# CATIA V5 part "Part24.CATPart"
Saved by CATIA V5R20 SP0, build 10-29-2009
Part number: 9SA200018-C_acabado
Revision: ANY
Definition: UNKNOWN
Nomenclature: 9SA200018-C_acabado
Source: Unknown
Bounding box of the stored display mesh (mm): x -10 to 10, y 0 to 18, z -10 to 10
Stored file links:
  C:\Users\Utente\Desktop\IO LAVORO\3D X SITO CF\CUMSA\3D files SA\SA 200018\Part24.CATPart
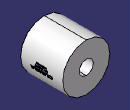
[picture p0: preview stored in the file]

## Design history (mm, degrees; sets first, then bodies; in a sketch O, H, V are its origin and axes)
Body1 "Envolver1" (main body)
  Solid1: solid without history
